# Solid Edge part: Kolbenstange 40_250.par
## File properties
Username: ahadarics
Dokumentum tartalom típus: 0
Author: ahadarics
Last saved by: ahadarics
Revision: 86
Sűrűség: 0,000 kg/m^3
Pontosság: 0,990
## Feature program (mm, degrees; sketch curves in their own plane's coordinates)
base feature "unnamed BaseFeature 1"
thread "unnamed Thread 1"
chamfer "Letörés_1"  SetBackValue2 = 20 deg
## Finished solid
Body 1: solid body, 21 faces, 32 edges, 14 vertices.
  Faces by surface: plane 8, cylinder 5, cone 4, torus 4
  Edges by curve: circle 17, line 9, curve on surface 4, ellipse 2
Bounding box of the edges (mm; curved faces can reach further): 40.000 x 40.000 x 378.000, from (-20, -20, -78) to (20, 20, 300).
Cylindrical faces by radius (mm): R5 x1, R6 x1, R7.75 x1, R8 x1, R20 x1
Conical faces (half-angle, radius in mm at the cone's reference point): 20 deg R6 x1, 30 deg R7.875 x1, 45 deg R19.6 x1, 60 deg R5.5 x1
Toroidal faces (ring radius, tube radius in mm): R5.4 r0.4 x2, R6.55 r1.2 x2
Planar faces by outward normal: +x 1, +z 3, -x 1, -z 1, oblique 2
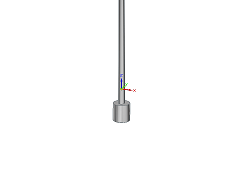
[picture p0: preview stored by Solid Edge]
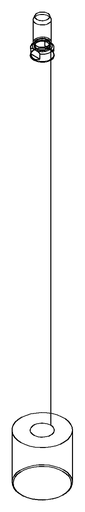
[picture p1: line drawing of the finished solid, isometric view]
